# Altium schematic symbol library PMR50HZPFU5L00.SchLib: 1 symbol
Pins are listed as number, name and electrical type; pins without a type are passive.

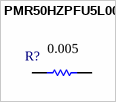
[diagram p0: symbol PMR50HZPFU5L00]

## PMR50HZPFU5L00
designator R?  value 0.005  (hidden comment: PMR50HZPFU5L00)
RES 0.005 OHM 1% 1W 2010; Manufacturer_Name: ROHM Semiconductor
footprint 2010L
pins: 1, 2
